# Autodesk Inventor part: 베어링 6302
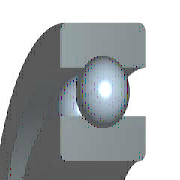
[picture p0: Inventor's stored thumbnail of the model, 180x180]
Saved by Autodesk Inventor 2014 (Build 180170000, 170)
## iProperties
IsCustomPart: 1
Created: 2012-02
Part Number: 베어링 6302
Material: 강철, 연강
Document SubType Name: Modeling
Standard: JIS B 1521
Designer: mdu-01
Standards Organization: JIS
Language: ko-KR
Size Designation: 6302 15x42x13
Categories: <MemberInstance><Categories><Category DisplayName="샤프트 부품" InternalName="7f7aeb1f-a693-4053-b835-cee3144e0d98" Mnemonic="SHFT"><Category DisplayName="베어링" Inter
Density: 1 g/cm^3
Appearance: 노란색
Author: mdu-01
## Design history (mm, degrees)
sketch "스케치" dims "d0" = 7.02 (= -0.26 x WD + 0.26 x BD)
  geometry: L1 (2.99, 14.25)-(10.01, 14.25); L2 (6.5, 14.25)-(6.5, 10.74); L3 (6.5, 14.25)-(6.5, 17.76); L4 (3.892, 11.901)-(0, 11.901); L5 (0, 7.5)-(13, 7.5); L6 (3.892, 16.599)-(0, 16.599); L7 (0, 21)-(13, 21); L8 (13, 7.5)-(13, 11.901); L9 (9.108, 11.901)-(13, 11.901); L10 (9.108, 16.599)-(13, 16.599); L11 (13, 21)-(13, 16.599); L12 (-1.4, 0)-(8.4, 0) reference; L13 (0, -0.3)-(0, 5.3) reference
  constraints: 22 end point, 4 point on line, 2 collinear, 2 perpendicular, 2 symmetric about line, 1 midpoint, 1 parallel, 14 other
  dimensions: "d9" = 15 diameter of L5 L12 (= WD); "d11" = 42 diameter of L7 L12 (= BD); "d12" = 13 distance between parallel lines of L8 L13 (= KB); "d13" = 23.802 diameter of L9 L12 (= 0.326 x BD + 0.674 x WD)
revolve "본체" stored, may be unused: angle "d6" = 90 deg
revolve "볼" stored, may be unused: angle "d7" = 90 deg
pattern_circular "IDS_ARRAYBALL[SIMPL:T]" dims angle "d3" = 360 deg
body "Solid1"
fillet "모깎기1" dims "d1" = 1 (= KRS)
other parameters: "WD" = 15 [user parameter; used in 5 equation terms], "BD" = 42 [user parameter; used in 5 equation terms], "KB" = 13 [user parameter; used in 1 equation term], "KRS" = 1 [user parameter; used in 1 equation term], "d4" = 0, "d5" = 0, "d8" = 0, "d14" = 0, "d15" = 0, "BBA" = 0 [user parameter], "BC0" = 5400000 [user parameter], "BC" = 1.14e+07 [user parameter], "BR" = 21 (= 0.5 x BD) [user parameter], "WR" = 7.5 (= 0.5 x WD) [user parameter]
